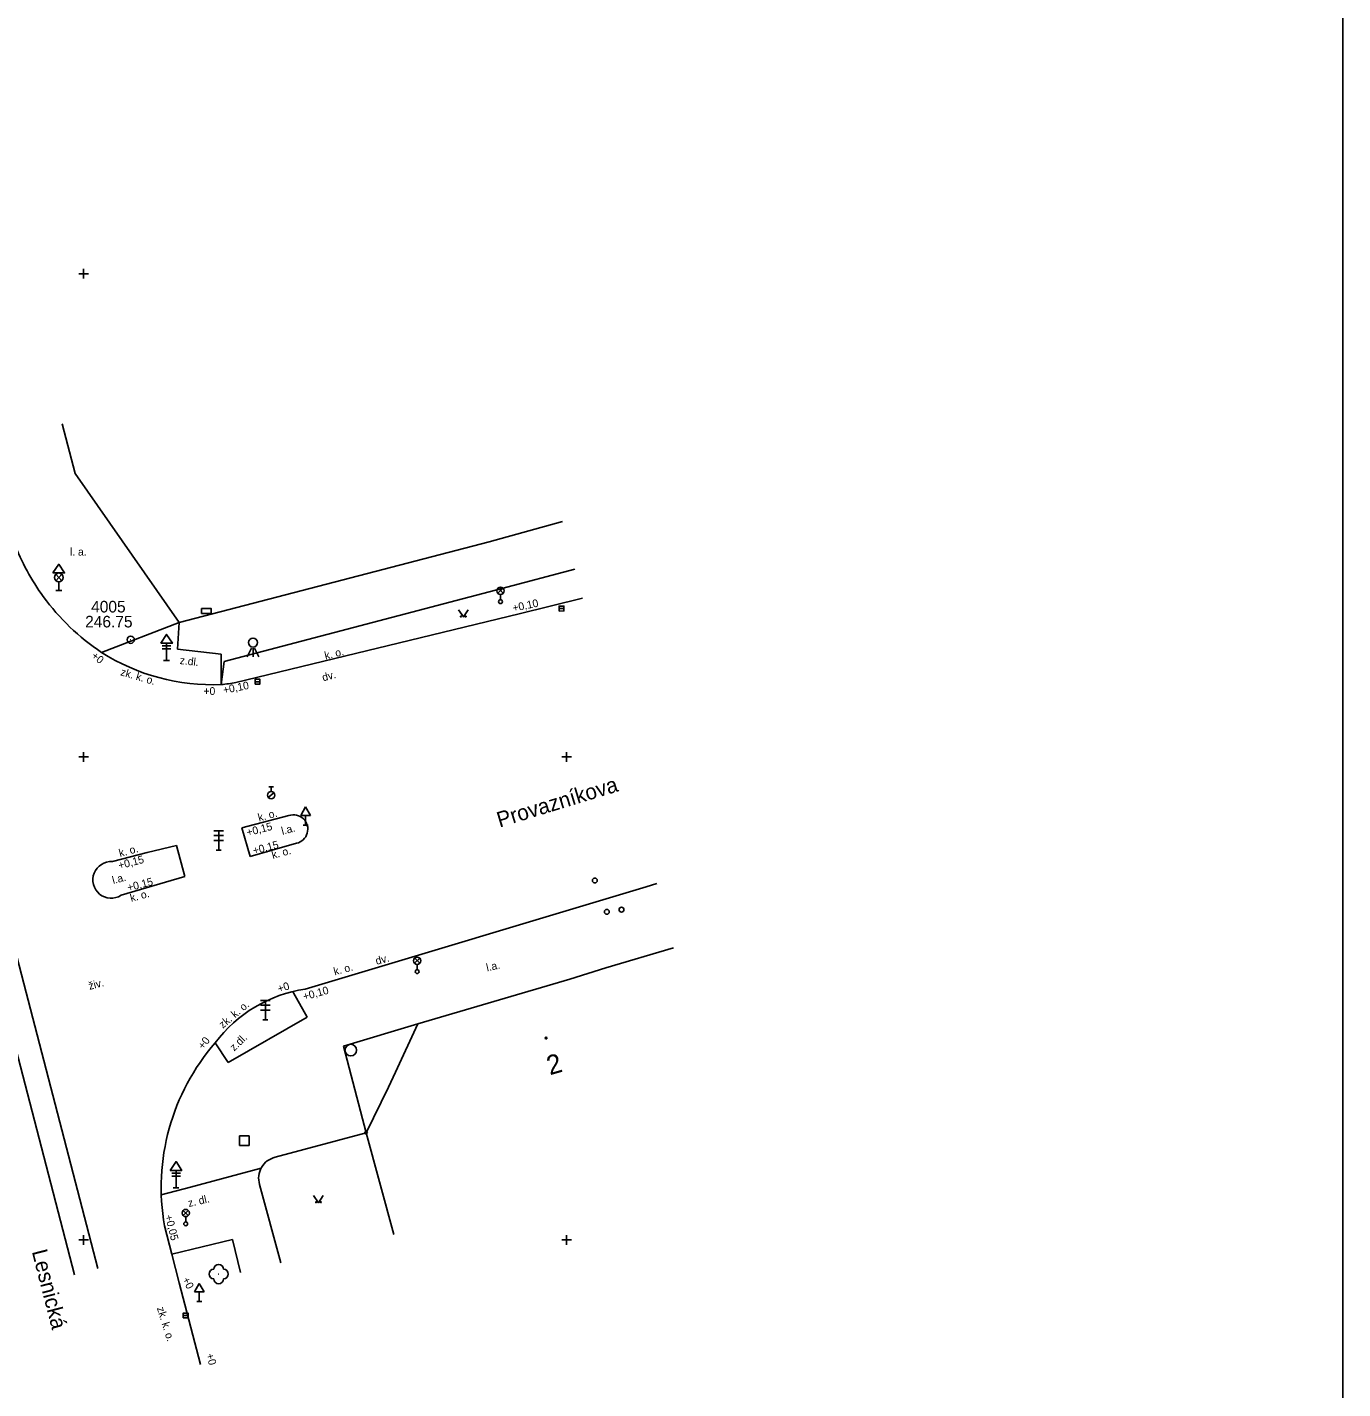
# Model space of a CAD drawing. Extents: x -597440 to -597210, y -1158961 to -1158436.
# Drawn here: x -597277.9 to -597209.8, y -1158907.7 to -1158837.2 of the extents above; entities that cross this region are included whole.
import ezdxf

# ---------------------------------------------------------------- set-up
doc = ezdxf.new("R2010")
doc.units = 0
for name, color, linetype in [('Vrstva 1', 7, 'Continuous'), ('Vrstva 10', 7, 'Continuous'), ('Vrstva 14', 7, 'Continuous'), ('Vrstva 15', 7, 'Continuous'), ('Vrstva 19', 7, 'Continuous'), ('Vrstva 2', 7, 'Continuous'), ('Vrstva 23', 7, 'Continuous'), ('Vrstva 24', 7, 'Continuous'), ('Vrstva 25', 7, 'Continuous'), ('Vrstva 26', 7, 'Continuous'), ('Vrstva 29', 7, 'Continuous'), ('Vrstva 4', 7, 'Continuous'), ('Vrstva 42', 7, 'Continuous'), ('Vrstva 43', 7, 'Continuous'), ('Vrstva 44', 7, 'Continuous'), ('Vrstva 49', 7, 'Continuous'), ('Vrstva 5', 7, 'Continuous'), ('Vrstva 50', 7, 'Continuous'), ('Vrstva 62', 7, 'Continuous'), ('Vrstva 7', 7, 'Continuous')]:
    doc.layers.add(name, color=color, linetype=linetype)

msp = doc.modelspace()

# ---------------------------------------------------------------- linework, layer by layer
at = {"layer": 'Vrstva 1'}
msp.add_lwpolyline([(-597358.318, -1158960.686), (-597209.818, -1158960.686), (-597209.818, -1158750.686), (-597358.318, -1158750.686)], close=True, dxfattribs=at)
at = {"layer": 'Vrstva 10'}
for p, q in [((-597276.111, -1158857.77), (-597275.433, -1158860.345)), ((-597275.433, -1158860.345), (-597270.051, -1158868.049)), ((-597270.051, -1158868.049), (-597254.01, -1158863.867)), ((-597260.372, -1158894.457), (-597265.078, -1158895.721)), ((-597265.889, -1158897.126), (-597264.792, -1158901.192))]:
    msp.add_line(p, q, dxfattribs=at)
msp.add_lwpolyline([(-597254.01, -1158863.867), (-597250.214, -1158862.822)], dxfattribs=at)
msp.add_arc((-597264.82, -1158896.806), 1.116, 103.36333, 196.64751, dxfattribs=at)
at = {"layer": 'Vrstva 14'}
for points in [[(-597255.588, -1158867.388), (-597255.338, -1158867.763), (-597255.088, -1158867.388)], [(-597263.091, -1158897.7), (-597262.841, -1158898.075), (-597262.591, -1158897.7)]]:
    msp.add_lwpolyline(points, dxfattribs=at)
for centre, radius in [((-597255.463, -1158867.738), 0.025), ((-597255.213, -1158867.738), 0.025), ((-597262.966, -1158898.05), 0.025), ((-597262.716, -1158898.05), 0.025), ((-597268.006, -1158901.768), 0.00025)]:
    msp.add_circle(centre, radius, dxfattribs=at)
for centre, start, end in [((-597268.006, -1158901.518), 0, 179.99999), ((-597268.256, -1158901.768), 89.99999, 269.99999), ((-597268.006, -1158902.018), 179.99999, 359.99999), ((-597267.756, -1158901.768), 270, 89.99999)]:
    msp.add_arc(centre, 0.25, start, end, dxfattribs=at)
at = {"layer": 'Vrstva 15'}
for centre, radius in [((-597251.054, -1158889.555), 0.0438), ((-597260.372, -1158894.457), 0.0625), ((-597260.372, -1158894.457), 0.0625)]:
    msp.add_circle(centre, radius, dxfattribs=at)
at = {"layer": 'Vrstva 19'}
for p, q in [((-597275.466, -1158901.802), (-597286.662, -1158858.767)), ((-597263.503, -1158877.595), (-597263.753, -1158878.028)), ((-597263.753, -1158878.028), (-597263.253, -1158878.028)), ((-597263.503, -1158877.595), (-597263.253, -1158878.028)), ((-597263.503, -1158878.528), (-597263.503, -1158878.028)), ((-597263.628, -1158878.528), (-597263.378, -1158878.528)), ((-597267.753, -1158878.825), (-597268.253, -1158878.825)), ((-597268.253, -1158879.075), (-597267.753, -1158879.075)), ((-597268.253, -1158879.325), (-597267.753, -1158879.325)), ((-597268.003, -1158879.825), (-597268.003, -1158878.825)), ((-597268.128, -1158879.825), (-597267.878, -1158879.825)), ((-597265.339, -1158887.604), (-597265.839, -1158887.604)), ((-597265.839, -1158887.854), (-597265.339, -1158887.854)), ((-597265.589, -1158888.604), (-597265.589, -1158887.604)), ((-597265.839, -1158888.104), (-597265.339, -1158888.104)), ((-597265.714, -1158888.604), (-597265.464, -1158888.604)), ((-597269.008, -1158902.262), (-597269.258, -1158902.695)), ((-597269.258, -1158902.695), (-597268.758, -1158902.695)), ((-597269.008, -1158902.262), (-597268.758, -1158902.695)), ((-597269.008, -1158903.195), (-597269.008, -1158902.695)), ((-597269.133, -1158903.195), (-597268.883, -1158903.195))]:
    msp.add_line(p, q, dxfattribs=at)
at = {"layer": 'Vrstva 2'}
for radius in [0.188, 0.00025]:
    msp.add_circle((-597272.56, -1158868.94), radius, dxfattribs=at)
at = {"layer": 'Vrstva 23'}
for p, q in [((-597266.419, -1158894.622), (-597266.919, -1158894.622)), ((-597266.919, -1158894.622), (-597266.919, -1158895.122)), ((-597266.419, -1158895.122), (-597266.419, -1158894.622)), ((-597266.919, -1158895.122), (-597266.419, -1158895.122))]:
    msp.add_line(p, q, dxfattribs=at)
at = {"layer": 'Vrstva 24'}
for p, q in [((-597265.416, -1158876.547), (-597265.166, -1158876.547)), ((-597265.291, -1158876.797), (-597265.291, -1158876.547)), ((-597265.438, -1158877.101), (-597265.143, -1158876.869))]:
    msp.add_line(p, q, dxfattribs=at)
for centre, radius in [((-597265.291, -1158876.985), 0.188), ((-597248.533, -1158881.4), 0.125)]:
    msp.add_circle(centre, radius, dxfattribs=at)
at = {"layer": 'Vrstva 25'}
for p, q in [((-597250.386, -1158867.327), (-597250.137, -1158867.326)), ((-597266.123, -1158871.111), (-597265.873, -1158871.111)), ((-597269.839, -1158903.911), (-597269.589, -1158903.911))]:
    msp.add_line(p, q, dxfattribs=at)
for points in [[(-597250.386, -1158867.453), (-597250.136, -1158867.452), (-597250.137, -1158867.201), (-597250.387, -1158867.202)], [(-597266.123, -1158871.236), (-597265.873, -1158871.236), (-597265.873, -1158870.986), (-597266.123, -1158870.986)], [(-597269.839, -1158904.036), (-597269.589, -1158904.036), (-597269.589, -1158903.786), (-597269.839, -1158903.786)]]:
    msp.add_lwpolyline(points, close=True, dxfattribs=at)
at = {"layer": 'Vrstva 26'}
for centre in [(-597247.915, -1158883.022), (-597247.155, -1158882.907)]:
    msp.add_circle(centre, 0.125, dxfattribs=at)
at = {"layer": 'Vrstva 29'}
for p, q in [((-597253.548, -1158866.537), (-597253.284, -1158866.273)), ((-597253.28, -1158866.536), (-597253.544, -1158866.271)), ((-597253.416, -1158866.868), (-597253.416, -1158866.593)), ((-597257.863, -1158885.684), (-597257.599, -1158885.42)), ((-597257.595, -1158885.683), (-597257.859, -1158885.418)), ((-597257.731, -1158886.015), (-597257.731, -1158885.74)), ((-597269.844, -1158898.739), (-597269.58, -1158898.475)), ((-597269.576, -1158898.738), (-597269.84, -1158898.473)), ((-597269.712, -1158899.07), (-597269.712, -1158898.795))]:
    msp.add_line(p, q, dxfattribs=at)
msp.add_lwpolyline([(-597268.889, -1158867.574), (-597268.389, -1158867.574), (-597268.389, -1158867.324), (-597268.889, -1158867.324)], close=True, dxfattribs=at)
for centre, radius in [((-597253.416, -1158866.406), 0.188), ((-597253.416, -1158866.968), 0.1), ((-597257.731, -1158885.552), 0.188), ((-597257.731, -1158886.115), 0.1), ((-597269.712, -1158898.607), 0.188), ((-597269.712, -1158899.17), 0.1)]:
    msp.add_circle(centre, radius, dxfattribs=at)
at = {"layer": 'Vrstva 4'}
for p, q in [((-597247.96, -1158885.926), (-597244.463, -1158884.879)), ((-597257.696, -1158888.817), (-597249.835, -1158886.508)), ((-597258.854, -1158891.311), (-597257.696, -1158888.817)), ((-597260.372, -1158894.457), (-597259.213, -1158892.094)), ((-597260.372, -1158894.457), (-597258.931, -1158899.728))]:
    msp.add_line(p, q, dxfattribs=at)
msp.add_lwpolyline([(-597257.696, -1158888.817), (-597261.543, -1158889.968), (-597260.372, -1158894.457)], dxfattribs=at)
msp.add_circle((-597261.167, -1158890.177), 0.3, dxfattribs=at)
at = {"layer": 'Vrstva 44'}
for p, q in [((-597276.132, -1158865.542), (-597276.432, -1158865.886)), ((-597276.432, -1158865.542), (-597276.132, -1158865.886)), ((-597276.282, -1158866.392), (-597276.282, -1158865.942)), ((-597276.432, -1158866.392), (-597276.132, -1158866.392)), ((-597270.924, -1158869.263), (-597270.476, -1158869.263)), ((-597270.924, -1158869.413), (-597270.481, -1158869.413)), ((-597270.704, -1158869.113), (-597270.704, -1158870.013)), ((-597266.298, -1158869.379), (-597266.524, -1158869.831)), ((-597266.224, -1158869.381), (-597266.224, -1158869.831)), ((-597266.149, -1158869.379), (-597265.924, -1158869.831)), ((-597270.854, -1158870.013), (-597270.554, -1158870.013)), ((-597270.213, -1158896.399), (-597270.213, -1158897.299)), ((-597270.433, -1158896.549), (-597269.985, -1158896.549)), ((-597270.433, -1158896.699), (-597269.99, -1158896.699)), ((-597270.363, -1158897.299), (-597270.063, -1158897.299))]:
    msp.add_line(p, q, dxfattribs=at)
msp.add_lwpolyline([(-597276.582, -1158865.486), (-597275.982, -1158865.486), (-597276.282, -1158865.036), (-597276.582, -1158865.486)], dxfattribs=at)
for points in [[(-597271.004, -1158869.118), (-597270.704, -1158868.663), (-597270.404, -1158869.118)], [(-597270.513, -1158896.404), (-597270.213, -1158895.949), (-597269.913, -1158896.404)]]:
    msp.add_lwpolyline(points, close=True, dxfattribs=at)
for centre, radius in [((-597276.282, -1158865.714), 0.228), ((-597266.224, -1158869.086), 0.234)]:
    msp.add_circle(centre, radius, dxfattribs=at)
at = {"layer": 'Vrstva 5'}
for p, q in [((-597249.835, -1158886.508), (-597247.96, -1158885.926)), ((-597259.213, -1158892.094), (-597258.854, -1158891.311))]:
    msp.add_line(p, q, dxfattribs=at)
at = {"layer": 'Vrstva 62'}
for p, q in [((-597275, -1158849.75), (-597275, -1158850.25)), ((-597275.25, -1158850), (-597274.75, -1158850)), ((-597275.25, -1158875), (-597274.75, -1158875)), ((-597275, -1158874.75), (-597275, -1158875.25)), ((-597250.25, -1158875), (-597249.75, -1158875)), ((-597250, -1158874.75), (-597250, -1158875.25)), ((-597275, -1158899.75), (-597275, -1158900.25)), ((-597250, -1158899.75), (-597250, -1158900.25)), ((-597275.25, -1158900), (-597274.75, -1158900)), ((-597250.25, -1158900), (-597249.75, -1158900))]:
    msp.add_line(p, q, dxfattribs=at)
at = {"layer": 'Vrstva 7'}
for p, q in [((-597274.256, -1158901.487), (-597285.452, -1158858.452)), ((-597253.35, -1158866.285), (-597249.571, -1158865.289)), ((-597267.724, -1158870.062), (-597253.35, -1158866.285)), ((-597252.455, -1158867.597), (-597249.178, -1158866.796)), ((-597274.069, -1158869.593), (-597270.051, -1158868.049)), ((-597270.132, -1158869.425), (-597270.051, -1158868.049)), ((-597267.11, -1158871.153), (-597252.455, -1158867.597)), ((-597270.132, -1158869.425), (-597267.878, -1158869.678)), ((-597267.878, -1158869.678), (-597267.868, -1158871.261)), ((-597267.868, -1158871.261), (-597267.724, -1158870.062)), ((-597266.808, -1158878.672), (-597264.37, -1158878.039)), ((-597266.808, -1158878.672), (-597266.377, -1158880.162)), ((-597266.377, -1158880.162), (-597263.978, -1158879.472)), ((-597273.504, -1158880.421), (-597271.701, -1158879.946)), ((-597270.182, -1158879.58), (-597271.701, -1158879.946)), ((-597270.182, -1158879.58), (-597269.759, -1158881.188)), ((-597269.759, -1158881.188), (-597273.055, -1158882.167)), ((-597264.175, -1158887.146), (-597264.139, -1158887.211)), ((-597263.428, -1158888.48), (-597264.139, -1158887.211)), ((-597267.518, -1158890.825), (-597263.428, -1158888.48)), ((-597268.186, -1158889.801), (-597267.518, -1158890.825)), ((-597265.808, -1158896.288), (-597269.466, -1158897.266)), ((-597270.976, -1158897.669), (-597269.466, -1158897.266)), ((-597270.426, -1158900.741), (-597270.809, -1158899.275)), ((-597270.426, -1158900.741), (-597267.287, -1158899.986)), ((-597267.287, -1158899.986), (-597266.868, -1158901.685)), ((-597270.045, -1158902.227), (-597270.426, -1158900.741)), ((-597268.941, -1158906.441), (-597270.045, -1158902.227))]:
    msp.add_line(p, q, dxfattribs=at)
msp.add_lwpolyline([(-597263.524, -1158887.016), (-597245.881, -1158881.719), (-597245.33, -1158881.554)], dxfattribs=at)
for centre, radius, start, end in [((-597267.401, -1158859.658), 11.976, 200.91433, 216.06328), ((-597267.49, -1158859.706), 11.876, 216.12799, 236.35866), ((-597268.317, -1158860.57), 10.7, 237.48348, 272.40539), ((-597268.767, -1158862.241), 9.065, 275.68849, 280.52938), ((-597264.136, -1158878.745), 0.744, 282.29044, 108.30774), ((-597273.567, -1158881.368), 0.949, 86.20281, 302.6405), ((-597262.448, -1158894.113), 7.178, 98.62559, 143.08118), ((-597259.546, -1158897.293), 11.436, 139.07067, 189.97845)]:
    msp.add_arc(centre, radius, start, end, dxfattribs=at)

# ---------------------------------------------------------------- texts
at = {"layer": 'Vrstva 2'}
msp.add_text('4005', height=0.6, rotation=360, dxfattribs=at).set_placement((-597274.607, -1158867.528))
msp.add_text('246.75', height=0.6, dxfattribs=at).set_placement((-597274.917, -1158868.303))
at = {"layer": 'Vrstva 42'}
for s, rotation, p in [('Provazníkova', 17, (-597253.465, -1158878.665)), ('Lesnická', 284.48073, (-597277.682, -1158900.598))]:
    msp.add_text(s, height=0.8, rotation=rotation, dxfattribs=at).set_placement(p)
at = {"layer": 'Vrstva 43'}
msp.add_text('2', height=1, rotation=15.87366, dxfattribs=at).set_placement((-597250.862, -1158891.482))
at = {"layer": 'Vrstva 49'}
msp.add_text('l. a.', height=0.4, dxfattribs=at).set_placement((-597275.703, -1158864.585))
for s, rotation, p in [('k. o.', 13.63908, (-597262.475, -1158869.966)), ('z.dl.', 353.59565, (-597270.037, -1158870.194)), ('zk. k. o.', 343.98032, (-597273.118, -1158870.776)), ('dv.', 15, (-597262.591, -1158871.096)), ('k. o.', 15, (-597265.914, -1158878.348)), ('l.a.', 14.78065, (-597264.703, -1158879.039)), ('k. o.', 15, (-597273.113, -1158880.184)), ('k. o.', 15, (-597265.203, -1158880.282)), ('l.a.', 14.78065, (-597273.46, -1158881.585)), ('k. o.', 15, (-597272.531, -1158882.507)), ('k. o.', 15, (-597261.997, -1158886.311)), ('dv.', 15, (-597259.829, -1158885.766)), ('l.a.', 12.80009, (-597254.107, -1158886.107)), ('živ.', 14.62948, (-597274.687, -1158887.064)), ('zk. k. o.', 40.30439, (-597267.789, -1158889.076)), ('z.dl.', 43.70794, (-597267.203, -1158890.254)), ('z. dl.', 12.73831, (-597269.548, -1158898.298)), ('zk. k. o.', 287.20912, (-597271.207, -1158903.531))]:
    msp.add_text(s, height=0.4, rotation=rotation, dxfattribs=at).set_placement(p)
at = {"layer": 'Vrstva 50'}
for s, rotation, p in [('+0,10', 11.7972, (-597252.752, -1158867.496)), ('+0', 321.69494, (-597274.629, -1158869.839)), ('+0,10', 11.16984, (-597267.74, -1158871.742)), ('+0,15', 14.62363, (-597266.506, -1158879.112)), ('+0,15', 14.62363, (-597266.18, -1158880.058)), ('+0,15', 14.62363, (-597273.148, -1158880.822)), ('+0,15', 14.62363, (-597272.681, -1158881.97)), ('+0', 18.44414, (-597264.882, -1158887.21)), ('+0,10', 15.3599, (-597263.584, -1158887.608)), ('+0', 52.36719, (-597268.802, -1158890.169)), ('+0,05', 284.24025, (-597270.794, -1158898.753)), ('+0', 296.40893, (-597269.898, -1158902.038)), ('+0', 285.74354, (-597268.662, -1158905.929))]:
    msp.add_text(s, height=0.4, rotation=rotation, dxfattribs=at).set_placement(p)
msp.add_text('+0', height=0.4, dxfattribs=at).set_placement((-597268.791, -1158871.795))

doc.saveas('drawing.dxf')
